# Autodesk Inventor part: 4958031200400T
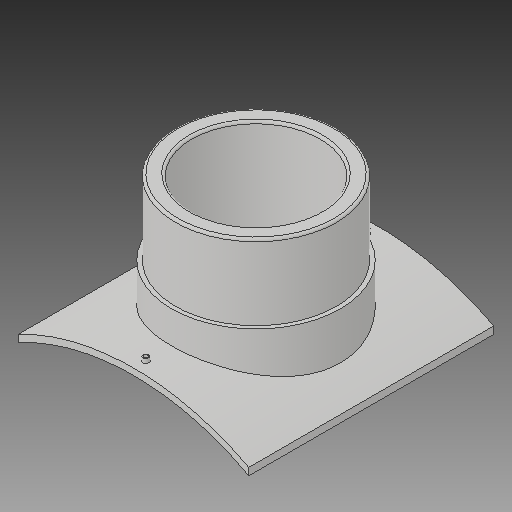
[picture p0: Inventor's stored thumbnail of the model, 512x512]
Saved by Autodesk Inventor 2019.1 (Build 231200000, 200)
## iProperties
Created: 2017-10
Part Number: 4958031200400T
Material: Generic
Description: PLASSON BRANCH SADDLE 1200x400
Document SubType Name: Modeling
Designer: KIM
Mass: 2754.05 g
Surface Area: 3037.44 cm^2
Volume: 2754.05 cm^3
Density: 1 g/cm^3
Appearance: Default
Author: KIM
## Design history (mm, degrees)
derived "495803.ipt"
feature "Solid1::495803.ipt"
tag "TaggingFeature1"
body "Solid1"
other parameters: "d1" = 16, "d2" = 574, "d4" = 0, "d12" = 625.6, "d13" = 14, "d14" = 274.5, "d16" = 5 deg, "d18" = 4, "d19" = 14, "d20" = 0, "d21" = 3, "d22" = 0, "d23" = 883, "d25" = 16, "d28" = 0, "d29" = 9.6, "d31" = 0, "d32" = 133.5, "d33" = 0, "d34" = 12, "d37" = 186.9, "d38" = 0, "d39" = 6, "B_" = 574, "H_" = 267, "x_" = 16, "D_" = 16
